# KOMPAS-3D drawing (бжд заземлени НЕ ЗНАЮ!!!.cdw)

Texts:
  ДП.11.213.07.000.00.ЭМ
  Телятник на 120 голов в СПК колхоз "Дзержинского" Даниловского МР Ярославской обл.
  УСЛОВНЫЕ ОБОЗНАЧЕНИЯ
  - пульт распределительнай марки ПР85-067
  - линия силовой электропроводки.
  № поз.
  Наименование помещения
  Площадь,
  Стойловое
  Веткабинет
  Инвентарная
  Венткамера
  Электрощитовая
  Служебная
  Санузел
  Кладовая дезосредств
  Фуражная
  Помещение для приготовления ЗЦМ
  Помещение для погрузки навоза в ТС
  Коридор
  ЭКСПЛИКАЦИЯ ПОМЕЩЕНИЙ
  ЯОУ-8501
  ввод в здание
  - ящик осветительный марки ЯОУ - 8501, рассчитанный
  на 6 отходящих групп освещения.
  - нагревательный элемент  номер по плану  мощность, кВт
  - электродвигатель  номер по плану  мощность, кВт
  ПР85-067
  - пульт управления комплектной установкой
  ВВГ (4 х 25)
  ЩУ-1
  - контур заземления.
  заливка
  Куракин
  ФГОУ ВПО ЯГСХА
  Телятник на 120 голов
  в СПК колхоз "Дзержинского"
  Даниловского МР Ярославской обл.
  Юрков
  Заземление
  ДП08Ф040200009Э0-
  Королёва
  Шмигель
  Орлов
Dimensions and other numbers on the sheet: 1; 2; 3; 4; 5; 6; 7; 8; 9; 10; 11; 12; 504; 16,6; 15,7; 29,5; 11,0; 25,0; 3,8; 12,2; 14,7; 27,5; 22,4; 30,1; 12000; 42000; 30000; 6000; 4500; 7500; 9000; 14000; 11000; 7000; 1:100; 0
